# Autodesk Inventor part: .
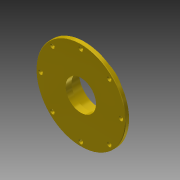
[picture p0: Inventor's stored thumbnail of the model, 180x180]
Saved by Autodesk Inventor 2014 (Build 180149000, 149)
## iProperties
Shininess: 64.0
Length Units: 11269
Angle Units: 11279
Time Units: 11290
Mass Units: 11283
Length Display Precision: 3
Angle Display Precision: 2
Created: 2002-09
Part Number: .
Description: top_cover.ipt.
Document SubType Name: Modeling
Density: 1 g/cm^3
Material: Generic
Appearance: Glossy - Gold
Density: 0.0
Volumn: 0.0
Area: 0.0
PropertySet Name: Model Information
Control State: 0
Master: False
Checked Out: False
ProtocolID: P00020918101120532
Protocol: P00020918101120532<@PID>[Version]<@EL>Version=2.2<@EL>[Synchronize]<@EL>ChangedVars=<@EL>[BaseView]<@EL>W2=350<@EL>Top=139<@EL>Left=337<@EL>OnTop=0<@EL>H2=462<@
Author: PaulN
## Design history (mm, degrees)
sketch "Sketch1" dims "d2" = 68
  geometry: L1 (11.034, 3.49)-(11.034, 37.49); C1 r 100 at (11.034, 3.49) reference
  constraints: 2 end point, 1 vertical, 1 vertical alignment, 3 other
extrude "Extrusion1" new body sketch "Sketch1" distance "d0" = 8; taper "d1" = 0 deg
workaxis "Work Axis1"
workplane "Work Plane1"
sketch "Sketch2"
  geometry: L1 (-34, 0)-(-34, -5); L2 (-34, -5)-(-41, -5); L3 (-41, -5)-(-41, -10); L4 (-41, -10)-(-45, -10); L5 (-45, -10)-(-45, -33); L6 (-45, -33)-(-55, -33); L7 (-55, -33)-(-55, 0); L8 (-55, 0)-(-34, 0); L9 (0, -41.2)-(0, 16.2) reference; L10 (34, 0)-(-34, 0) reference
  constraints: 16 end point, 6 parallel, 2 perpendicular
  dimensions: "d3" = 10 distance between parallel lines of L7 L5; "d4" = 4 distance between parallel lines of L3 L5; "D_Out" = 90 diameter of L5 L9; "d11" = 5 distance between parallel lines of L8 L2; "d12" = 5 distance of L2.end L3.end; "B" = 23 distance of L4.end L5.end
revolve "Revolution1" sketch "Sketch2" stored, may be unused: angle "d7" = 90 deg
sketch "Sketch3"
  geometry: C1 r 3 at (90, 0); C2 r 34 at (0, 0) reference; C3 r 100 at (0, 0) reference
  constraints: 1 centre point
extrude "Extrusion2" cut sketch "Sketch3" stored distance "d14" = 10; taper "d15" = 0 deg
chamfer "Chamfer1" distance "d16" = 2; stored, may be unused: second distance "d17" = 2, angle "d23" = 45 deg
pattern_circular "Circular Pattern1" dims angle "d20" = 360 deg
chamfer "Chamfer2" distance "d21" = 1; stored, may be unused: second distance "d22" = 1, angle "d24" = 45 deg
body "Solid1"
